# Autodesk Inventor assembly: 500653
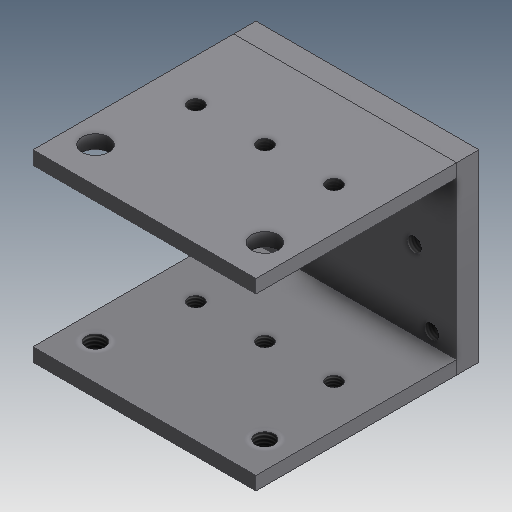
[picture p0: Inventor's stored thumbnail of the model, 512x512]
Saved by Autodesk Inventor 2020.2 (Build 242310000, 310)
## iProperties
Created: 2000-02
Part Number: 500653
Document SubType Name: Assembly
Designer: sspink
Mass: 1449.73 g
Surface Area: 619.772 cm^2
Volume: 185.15 cm^3
Density: 7.83 g/cm^3
Control State: 0
Checked Out: False
Master: False
Shininess: 0.0
Length Units: 11272
Angle Units: 11279
Time Units: 11290
Mass Units: 11286
Length Display Precision: 3
Angle Display Precision: 2
Compacted: True
Dimensions: 3,2x3,9x3,9 in
Mass: 3,196 lb
DocNumber: 500653.iam
Folder: 01 - Themengebiete\Simplification\01 - Packaging machine\
VDS_Category: 3D Komponenten
Density: 0.0
Volumn: 0.0
Area: 0.0
PropertySet Name: Model Information
Author: sspink
Revision Number: -
Title: 500653
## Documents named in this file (4)
- D:\07 - DEMODATEN\OTX 2019 - Dataset - UPDATE - Dez2019\Designs\07-Packing machine\500653.iam
- D:\07 - DEMODATEN\OTX 2019 - Dataset - UPDATE - Dez2019\Designs\07-Packing machine\Parts\ADSK-011630.ipt
- D:\07 - DEMODATEN\OTX 2019 - Dataset - UPDATE - Dez2019\Designs\07-Packing machine\Parts\ADSK-011628.ipt
- D:\07 - DEMODATEN\OTX 2019 - Dataset - UPDATE - Dez2019\Designs\07-Packing machine\Parts\ADSK-011629.ipt
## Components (3 placed, 3 different names)
1. ADSK-011630:1 — Mate:1, Flush:1, Flush:4, Passend:2, Passend:3, Fluchtend:5
2. ADSK-011628:1 — Mate:1, Flush:1, Flush:4
3. ADSK-011629:1 — Passend:2, Passend:3, Fluchtend:5
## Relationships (6: Mate 3, Flush 3)
- Mate:1: ADSK-011630:1 ↔ ADSK-011628:1
- Flush:1: ADSK-011630:1 ↔ ADSK-011628:1
- Flush:4: ADSK-011630:1 ↔ ADSK-011628:1
- Passend:2 [Mate]: ADSK-011630:1 ↔ ADSK-011629:1
- Passend:3 [Mate]: ADSK-011630:1 ↔ ADSK-011629:1
- Fluchtend:5 [Flush]: ADSK-011630:1 ↔ ADSK-011629:1
